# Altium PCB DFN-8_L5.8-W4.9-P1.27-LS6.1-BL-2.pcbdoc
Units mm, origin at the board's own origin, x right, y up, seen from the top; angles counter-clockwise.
Board outline 18.06 x 19.82 mm, 2 copper layers (Top Layer, Bottom Layer), stack 0 mm thick; 1 components, 0 nets, 9 pads, 0 vias.
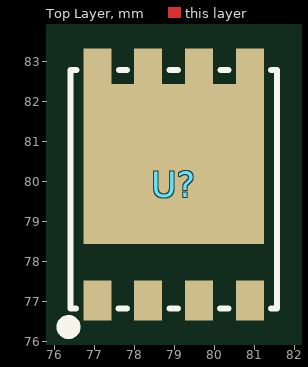
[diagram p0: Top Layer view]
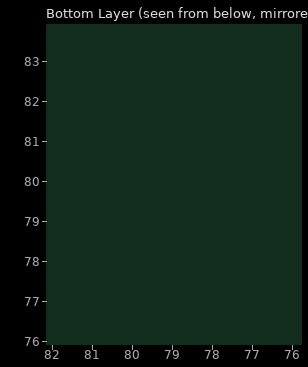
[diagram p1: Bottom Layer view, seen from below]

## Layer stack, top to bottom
Top Layer: signal copper (thickness not stored)
Bottom Layer: signal copper (thickness not stored)

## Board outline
87.907,69.85 69.85,69.85 69.85,89.666 87.907,89.666

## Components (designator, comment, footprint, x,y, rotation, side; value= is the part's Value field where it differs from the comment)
U? "" DFN-8_L5.8-W4.9-P1.27-LS6.1-BL-2 78.977,79.916 r0 top

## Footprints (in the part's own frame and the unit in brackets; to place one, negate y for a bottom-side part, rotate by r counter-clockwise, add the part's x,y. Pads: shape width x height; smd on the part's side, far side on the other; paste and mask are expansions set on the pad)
DFN-8_L5.8-W4.9-P1.27-LS6.1-BL-2 [mm]
  rect 0.7x1 smd paste-100 mask+0.05: 1(-1.905,-2.9) 2(-0.635,-2.9) 3(0.635,-2.9) 4(1.905,-2.9) 5(1.905,2.9) 6(0.635,2.9) 7(-0.635,2.9) 8(-1.905,2.9)
  rect 4.51x4 smd paste-100 mask+0.05: 8(0,0.508)
  silkscreen extent -2.78,-3.72 2.58,2.86

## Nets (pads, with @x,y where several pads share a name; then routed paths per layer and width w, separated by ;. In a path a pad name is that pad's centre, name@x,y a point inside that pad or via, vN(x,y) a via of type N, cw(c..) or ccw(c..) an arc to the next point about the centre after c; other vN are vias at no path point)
pads on no net: U?.1 U?.2 U?.3 U?.4 U?.5 U?.6 U?.7 U?.8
